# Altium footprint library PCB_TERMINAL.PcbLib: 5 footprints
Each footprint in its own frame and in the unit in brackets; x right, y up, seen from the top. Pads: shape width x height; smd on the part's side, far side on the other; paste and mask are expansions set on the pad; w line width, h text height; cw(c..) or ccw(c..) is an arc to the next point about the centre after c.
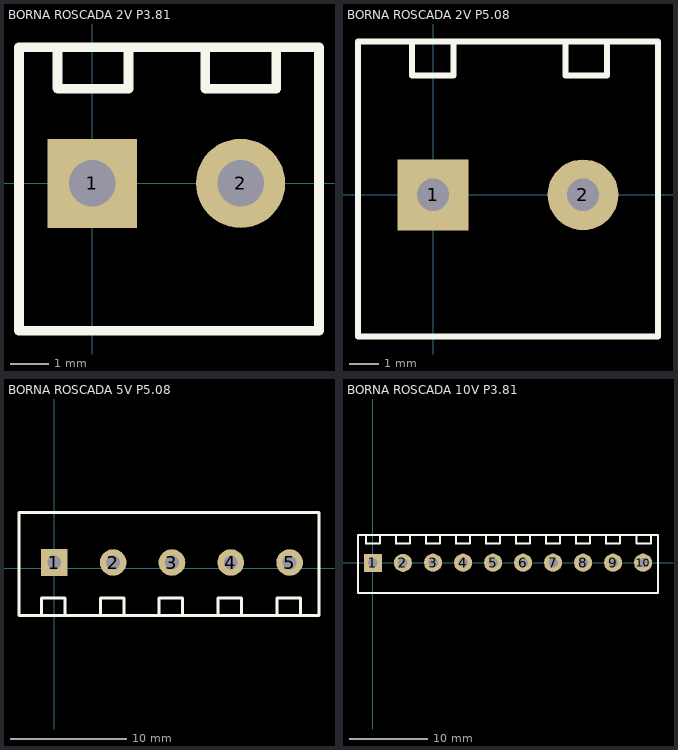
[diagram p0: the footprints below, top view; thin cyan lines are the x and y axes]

## BORNA ROSCADA 2V P3.81 [mm] "Terminal roscado vertical 2 vías,3.81mm"
pads (2):
  rect 2.3x2.3 hole 1.2: 1(0,0)
  round 2.3 hole 1.2: 2(3.82,0)
Top Overlay:
  lines w0.254: -0.9,3.51 -0.9,2.45 ; 0.93,3.5 0.93,2.45 ; 2.91,3.51 2.91,2.45 2.92,2.44 4.74,2.44 4.74,2.45 4.74,3.5 ; -0.9,2.45 -0.89,2.44 ; -0.9,2.45 -0.89,2.44 ; -0.89,2.44 0.93,2.44 ; 0.93,2.44 0.93,2.45 ; 0.93,2.44 0.93,2.45 ; -1.89,-3.8 -1.89,3.51 5.842,3.51 5.842,-3.8 -1.89,-3.8
3D body: height 2.99, standoff -9.01, extent -1.873,-3.944 5.937,3.556

## BORNA ROSCADA 2V P5.08 [mm] "Terminal roscado vertical 2 vías,5.08mm"
height 10
pads (2):
  rect 2.4x2.4 hole 1.1: 1(0,0)
  round 2.4 hole 1.1: 2(5.08,0)
Top Overlay:
  lines w0.2: -0.71,5.2 -0.71,4.05 0.69,4.05 0.69,5.2 ; 4.49,5.2 4.49,4.05 5.89,4.05 5.89,5.2 ; -2.54,-4.8 7.62,-4.8 7.62,5.2 -2.54,5.2 -2.54,-4.8

## BORNA ROSCADA 5V P5.08 [mm] "Terminal roscado vertical 5 vías,5.08mm"
pads (5):
  rect 2.3x2.3 hole 1.2: 1(0,0.508)
  round 2.3 hole 1.2: 2(5.08,0.508) 3(10.16,0.508) 4(15.24,0.508) 5(20.32,0.508)
Top Overlay:
  lines w0.254: -1.102,-4.064 -1.102,-2.596 ; -1.102,-2.54 0.93,-2.54 ; 0.93,-4.064 0.93,-2.596 ; 3.978,-3.912 3.978,-2.596 ; 3.978,-2.54 6.01,-2.54 ; 6.01,-3.912 6.01,-2.596 ; 9.058,-3.912 9.058,-2.596 ; 9.058,-2.54 11.09,-2.54 ; 11.09,-3.912 11.09,-2.596 ; 14.138,-3.912 14.138,-2.596 ; 14.138,-2.54 16.17,-2.54 ; 16.17,-3.912 16.17,-2.596 ; 19.218,-3.912 19.218,-2.596 ; 19.218,-2.54 21.25,-2.54 ; 21.25,-3.912 21.25,-2.596 ; -3.048,-4.064 22.86,-4.064 22.86,4.826 -3.048,4.826 -3.048,-4.064
3D body: height 13.1, standoff -3.9, extent -3.069,-4.064 22.881,4.936

## BORNA ROSCADA 10V P3.81 [mm] "Terminal roscado vertical 2 vías,3.81mm"
pads (10):
  rect 2.3x2.3 hole 1.2: 1(0,0)
  round 2.3 hole 1.2: 2(3.82,0) 3(7.64,0.02) 4(11.45,0.02) 5(15.26,0.02) 6(19.07,0.02) 7(22.88,0.02) 8(26.69,0.02) 9(30.5,0.02) 10(34.31,0.02)
Top Overlay:
  lines w0.254: -0.9,3.51 -0.9,2.45 ; 0.93,3.5 0.93,2.45 ; 2.91,3.51 2.91,2.45 2.92,2.44 4.74,2.44 4.74,2.45 4.74,3.5 ; 6.72,3.51 6.72,2.45 6.73,2.44 8.55,2.44 8.55,2.45 8.55,3.5 ; 10.53,3.51 10.53,2.45 10.54,2.44 12.36,2.44 12.36,2.45 12.36,3.5 ; 14.34,3.51 14.34,2.45 14.35,2.44 16.17,2.44 16.17,2.45 16.17,3.5 ; 18.15,3.51 18.15,2.45 18.16,2.44 19.98,2.44 19.98,2.45 19.98,3.5 ; 21.96,3.51 21.96,2.45 21.97,2.44 23.79,2.44 23.79,2.45 23.79,3.5 ; 25.77,3.51 25.77,2.45 25.78,2.44 27.6,2.44 27.6,2.45 27.6,3.5 ; 29.58,3.51 29.58,2.45 29.59,2.44 31.41,2.44 31.41,2.45 31.41,3.5 ; 33.5,3.51 33.5,2.45 33.51,2.44 35.33,2.44 35.33,2.45 35.33,3.5 ; -0.9,2.45 -0.89,2.44 ; -0.9,2.45 -0.89,2.44 ; -0.89,2.44 0.93,2.44 ; 0.93,2.44 0.93,2.45 ; 0.93,2.44 0.93,2.45 ; -1.89,-3.8 -1.89,3.51 36.21,3.51 36.21,-3.8 -1.89,-3.8
3D body: height 8.5, standoff -3.5, extent -1.905,-3.683 36.195,3.617

## PCBComponent_1 [mm]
